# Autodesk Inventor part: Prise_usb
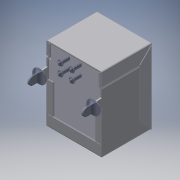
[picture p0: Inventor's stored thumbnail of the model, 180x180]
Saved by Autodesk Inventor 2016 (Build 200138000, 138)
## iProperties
Created: 2018-03
Part Number: Prise_usb
Material: Générique
Document SubType Name: Modeling
Designer: Bruno
Density: 1 g/cm^3
Appearance: Par défaut
Author: Bruno
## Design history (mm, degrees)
feature "Composite1"
body "Srf1"
